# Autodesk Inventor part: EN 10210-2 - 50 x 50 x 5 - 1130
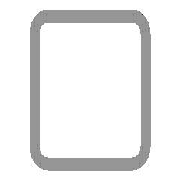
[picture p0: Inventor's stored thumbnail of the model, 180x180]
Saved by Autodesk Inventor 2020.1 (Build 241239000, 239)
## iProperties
Created: 2019-01
Part Number: EN 10210-2 - 50 x 50 x 5 - 1130
Material: Stahl, weich
Description: Rohrleitung
Document SubType Name: Modeling
Standard: DIN
Designer: lutzd
Standard Revision: 2006-07
Standards Organization: DIN
Language: de-DE
Size Designation: 50 x 50 x 5
Categories: <MemberInstance><Categories><Category DisplayName="Profile" InternalName="089c4875-fa83-4c05-b084-43b9cc11f5ed" Mnemonic="GRDR"><CategoryParameter DisplayName="
Stock Number: 50 x 50 x 5
Mass: 7745.5 g
Surface Area: 3842.96 cm^2
Volume: 986.687 cm^3
Density: 7.85 g/cm^3
Appearance: Semi-Polished(8)
IsCustomPart: 1
_CCFamilyMember: 16
_CCFamilyDisplayName: DIN EN 10210-2 (USAS B17.1 quadratisch) - Rohrleitung — In Klammern angegebene Größen wurden aufgehoben
_FrameMemberDoc: Frame Member File
_Version: 15.0.0
_GetPNFromCC: 1
Title: Profil-Bauteil
Author: lutzd
Revision Number: -
G_W: 50,000 mm
G_H: 50,000 mm
+506796A4-962A-44B1-93F6-DA31BA53D3D8+SCHNITTDETAIL1: Schnittwinkel 90,00 grd
G_L: 1130,000 mm
+0691C9BF-E22A-422E-B905-A4CF7C61FDF4+SCHNITTDETAIL4: Schnittwinkel 90,00 grd
DocNumber: ADSK-014251
Folder: .
Dimensions: 50x50x1130 mm
Mass: 7,745 kg
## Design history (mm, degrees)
node "Startebene"
node "Endebene"
sketch "Skizze"
  geometry: L1 (-25, -17.5)-(-25, 17.5); L2 (-17.5, 25)-(17.5, 25); L3 (25, 17.5)-(25, -17.5); L4 (17.5, -25)-(-17.5, -25); L5 (-15, 20)-(15, 20); L6 (20, 15)-(20, -15); L7 (15, -20)-(-15, -20); L8 (-20, -15)-(-20, 15); L9 (0, 37.175)-(0, -37.175) reference; L10 (-37.175, 0)-(37.175, 0) reference; A1 r 7.5 centre (-17.5, -17.5) between (-25, -17.5) and (-17.5, -25); A2 r 7.5 centre (-17.5, 17.5) between (-17.5, 25) and (-25, 17.5); A3 r 7.5 centre (17.5, 17.5) between (25, 17.5) and (17.5, 25); A4 r 7.5 centre (17.5, -17.5) between (17.5, -25) and (25, -17.5); A5 r 5 centre (-15, -15) between (-20, -15) and (-15, -20); A6 r 5 centre (-15, 15) between (-15, 20) and (-20, 15); A7 r 5 centre (15, 15) between (20, 15) and (15, 20); A8 r 5 centre (15, -15) between (15, -20) and (20, -15)
  constraints: 16 end point, 16 point on circle, 16 tangent, 8 centre point, 6 equal radius, 4 parallel, 2 perpendicular, 2 other
  dimensions: "d7" = 7.5 radius of A1 (= G_IR); "d10" = 50 distance between parallel lines of L2 L4 (= G_H); "d11" = 50 distance between parallel lines of L1 L3 (= G_W); "d12" = 5 distance between parallel lines of L3 L6 (= G_T); "d15" = 25 distance between parallel lines of L2 L10 (= 0.5 x d10); "d16" = 25 distance between parallel lines of L9 L3 (= 0.5 x d11); "d19" = 5 radius of A5 (= G_T); "d20" = 5 distance between parallel lines of L4 L7 (= G_T)
extrude "Körper" new body sketch "Skizze" stored distance "d3" = 1130 (= G_L); taper "d4" = 0 deg
node "Driven Length"
  sketch "Sketch3"
    geometry: L1 (0, 0)-(10, 0) reference
    constraints: 2 end point, 1 horizontal
  workplane "Work Plane3"
  sketch "Sketch4"
    geometry: L1 (-2, -428)-(12, -428) reference; L2 (-2, 702)-(12, 702) reference
    dimensions: "d18" = 1130 distance between parallel lines of L1 L2 (derived)
workplane "Arbeitsebene4"
feature "Trennen1"
workplane "Arbeitsebene7"
feature "Trennen4"
body "Solid1"
other parameters: "G_W" = 50 [user parameter; used in 1 equation term], "G_H" = 50 [user parameter; used in 1 equation term], "G_T" = 5 [user parameter; used in 3 equation terms], "G_IR" = 7.5 [user parameter; used in 1 equation term], "G_L" = 1130 (= d18) [user parameter; used in 1 equation term], "G_OFFSET_START" = 428 [user parameter; used in 1 equation term], "G_OFFSET_END" = 384 [user parameter; used in 1 equation term], "d13" = -428 (= -G_OFFSET_START), "d14" = 702 (= G_OFFSET_END + B_L), "B_L" = 318 [user parameter; used in 1 equation term], "d17" = 90 deg
